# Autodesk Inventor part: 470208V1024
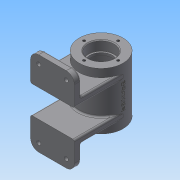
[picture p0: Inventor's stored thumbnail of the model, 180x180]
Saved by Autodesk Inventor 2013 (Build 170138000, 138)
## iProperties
Created: 2017-02
Part Number: 470208V1024
Material: Generic
Document SubType Name: Modeling
Designer: Administrator
Density: 1 g/cm^3
Author: Administrator
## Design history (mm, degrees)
sketch "스케치1"
  geometry: C1 r 27 at (0, 0); 1 further point
  constraints: 1 centre point, 1 coincident
  dimensions: "d0" = 54 diameter of C1
extrude "돌출1" new body sketch "스케치1" stored distance "d1" = 70; taper "d2" = 0 deg
node "작업 평면1"
sketch "스케치2"
  geometry: L1 (27, 17)-(-27, 17); L2 (-27, 17)-(-27, 52); L3 (-27, 52)-(27, 52); L4 (27, 52)-(27, 17); 1 further point
  constraints: 8 end point, 2 parallel, 1 horizontal, 1 perpendicular
  dimensions: "d4" = 17 distance from line of point (0, 0) L1; "d5" = 54 distance of L2.end L3.end; "d6" = 27 distance from line of point (0, 0) L2; "d7" = 35 distance of L1.end L2.end
extrude "돌출2" join sketch "스케치2" distance "d8" = 8; taper "d9" = 0 deg
sketch "스케치3"
  geometry: L1 (-27, -17)-(27, -17); L2 (27, -17)-(27, -25); L3 (27, -25)-(-27, -25); L4 (-27, -25)-(-27, -17); 1 further point
  constraints: 8 end point, 2 parallel, 1 horizontal, 1 perpendicular
  dimensions: "d10" = 54 distance of L2.end L3.end; "d11" = 8 distance of L1.end L2.end
extrude "돌출3" join sketch "스케치3" stored distance "d12" = 8; taper "d13" = 0 deg
sketch "스케치4"
  geometry: C1 r 2.5 at (-17, -42); 1 further point
  constraints: 1 centre point
  dimensions: "d14" = 5 diameter of C1; "d15" = 17 horizontal distance of point (0, 0) C1.centre; "d16" = 42 vertical distance of point (0, 0) C1.centre
extrude "돌출4" cut sketch "스케치4" distance "d17" = 8; taper "d18" = 0 deg
sketch "스케치6"
  geometry: L1 (-12.5, -44.598)-(-17, -47.196); L2 (-17, -47.196)-(-21.5, -44.598); L3 (-21.5, -44.598)-(-21.5, -39.402); L4 (-21.5, -39.402)-(-17, -36.804); L5 (-17, -36.804)-(-12.5, -39.402); L6 (-12.5, -39.402)-(-12.5, -44.598); C1 r 2.5 at (-17, -42) reference; 3 further points
  constraints: 12 end point, 1 midpoint, 13 other
extrude "돌출5" cut sketch "스케치6" distance "d20" = 3; taper "d21" = 0 deg
fillet "모깎기1" dims "d22" = 10
node "작업 평면2"
sketch "스케치7"
  geometry: L1 (27, 35)-(-27, 35) reference; C1 r 5 at (0, 10); 1 further point
  constraints: 1 centre point
  dimensions: "d24" = 10 diameter of C1; "d25" = 25 distance from line of L1 C1.centre
extrude "돌출6" join sketch "스케치7" stored distance "d26" = 3; taper "d27" = 0 deg
sketch "스케치8"
  geometry: C1 r 27 at (0, 0) reference; C2 r 16 at (0, 0)
  constraints: 1 centre point, 1 coincident
  dimensions: "d28" = 32 diameter of C2
extrude "돌출7" cut sketch "스케치8" distance "d29" = 12; taper "d30" = 0 deg
sketch "스케치9"
  geometry: C1 r 16 at (0, 0) reference; C2 r 14 at (0, 0)
  constraints: 1 centre point, 1 coincident
  dimensions: "d31" = 28 diameter of C2
extrude "돌출8" cut sketch "스케치9" distance "d32" = 3; taper "d33" = 0 deg
sketch "스케치10"
  geometry: C1 r 14 at (0, 0) reference; C2 r 22 at (0, 0)
  constraints: 1 centre point, 1 coincident
  dimensions: "d34" = 44 diameter of C2
extrude "돌출9" cut sketch "스케치10" distance "d35" = 40; taper "d36" = 0 deg
hole "구멍1" diameter "d39" = 5.188; stored, may be unused: countersink angle "d43" = 90 deg, drill point angle "d45" = 118 deg; dims "d40" = 30, "d41" = 4, "d42" = 2, "d44" = 30, "d63" = 10, "d64" = 10
node "작업 평면3"
sketch "스케치12"
  geometry: 2 further points
  constraints: 1 coincident, 1 other
feature "엠보싱1" sketch "스케치12" dims "d12" = 8, "d13" = 0, "d47" = 0.5, "d48" = 0
sketch "스케치13"
  geometry: L1 (0, 0)-(-16.339, -25.16); L2 (0, 0)-(30, 0)
  constraints: 4 end point, 1 equal length, 1 horizontal
  dimensions: "d49" = 30 distance of L1.start L1.end; "d50" = 123 deg angle of L1 L2
node "작업 평면4"
sketch "스케치14"
  geometry: C1 r 6 at (0, 0); 1 further point
  constraints: 1 centre point, 1 coincident
  dimensions: "d51" = 12 diameter of C1
extrude "돌출10" join sketch "스케치14" stored distance "d52" = 40; taper "d53" = 0 deg
sketch "스케치15"
  geometry: C1 r 6 at (0, 0) reference
sketch "스케치16"
  geometry: C1 r 6 at (0, 0) reference
hole "구멍2" diameter "d56" = 5.188; stored, may be unused: countersink angle "d60" = 90 deg, drill point angle "d62" = 118 deg; dims "d54" = 10, "d55" = 10, "d57" = 30, "d58" = 4, "d59" = 2, "d61" = 30
sketch "스케치17"
  geometry: L1 (0, 0)-(0, 21); C1 r 27 at (0, 0) reference; 1 further point
  constraints: 2 end point, 1 coincident, 1 vertical
  dimensions: "d65" = 21 distance of L1.start L1.end
hole "구멍3" sketch "스케치17" at (0, 21) diameter "d66" = 3.242; stored, may be unused: countersink angle "d70" = 90 deg, drill point angle "d72" = 118 deg; dims "d67" = 8, "d68" = 4, "d69" = 2, "d71" = 10
fillet "모깎기2" dims "d76" = 10
fillet "모깎기3" dims "d77" = 2
fillet "모깎기4" dims "d78" = 2
fillet "모깎기5" dims "d79" = 2
fillet "모깎기6" dims "d80" = 2
fillet "모깎기7" dims "d81" = 2
fillet "모깎기8" dims "d82" = 0.3
chamfer "모따기1" distance "d83" = 1; stored, may be unused: second distance "d84" = 2, angle "d85" = 45 deg
fillet "모깎기9" dims "d86" = 2
fillet "모깎기10" dims "d87" = 2
fillet "모깎기11" dims "d88" = 2
node "솔리드1"
mirror "대칭1"
mirror "대칭2"
mirror "대칭3"
pattern_circular "원형 패턴1" dims angle "d74" = 360 deg
mirror "대칭4"
other parameters: "d23" = 32, "d46" = 27
